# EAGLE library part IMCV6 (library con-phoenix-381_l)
Invertierter Mini-Combicon 3.81mm vertikal 6-polig IMCV 1,5/6-G-3,81 (ohne Gegenstecker)
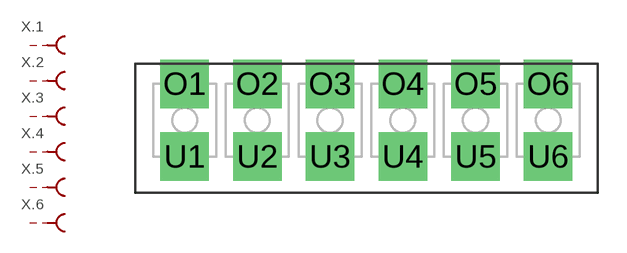
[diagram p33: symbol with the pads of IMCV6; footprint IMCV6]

Designator prefix X; gates .3=MCBU .2=MCBU .1=MCBU .4=MCBU .5=MCBU .6=MCBU

## IMCV6  [IMCV6]
O1  .1:S  pas
O2  .2:S  pas
O3  .3:S  pas
O4  .4:S  pas
O5  .5:S  pas
O6  .6:S  pas
U1  .1:SK  pas
U2  .2:SK  pas
U3  .3:SK  pas
U4  .4:SK  pas
U5  .5:SK  pas
U6  .6:SK  pas

## Footprint IMCV6 (pad centres in mm)
Mini-Combicon 3.81mm vertical 6-polig invertiert (ohne Gegenstecker)
drill 1.3 pad 2.54 square: O1 -9.525,1.905; O2 -5.715,1.905; O3 -1.905,1.905; O4 1.905,1.905; O5 5.715,1.905; O6 9.525,1.905; U1 -9.525,-1.905; U2 -5.715,-1.905; U3 -1.905,-1.905; U4 1.905,-1.905; U5 5.715,-1.905; U6 9.525,-1.905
